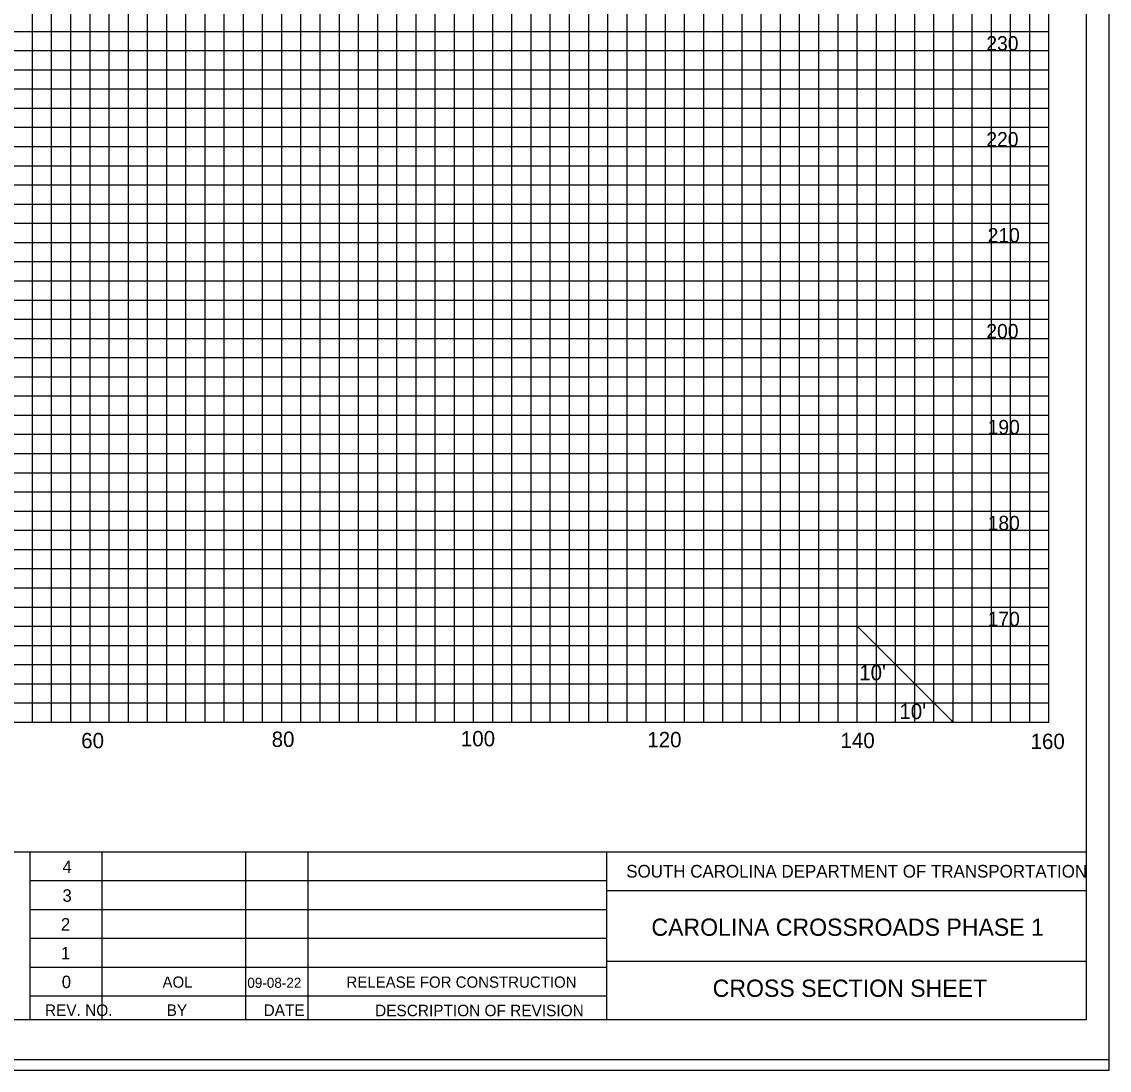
# Model space of a CAD drawing. Extents: x 967 to 1326, y 964 to 3144.
# Drawn here: x 1212.9 to 1326.3, y 963.7 to 1073 of the extents above; entities that cross this region are included whole.
import ezdxf

# ---------------------------------------------------------------- set-up
doc = ezdxf.new("R2010")
doc.units = 0
for name, color, linetype in [('Default', 7, 'Continuous'), ('RD_GPK_XS_Cell', 7, 'Continuous'), ('RD_XS_ExGround', 7, 'Continuous'), ('RD_XS_ExPaveRet', 7, 'Continuous'), ('RD_XS_Misc_Line', 7, 'Continuous'), ('RD_XS_TX_Elev_EX', 7, 'Continuous'), ('RD_XS_TX_Elev_PR', 7, 'Continuous'), ('RD_XS_TX_Station', 7, 'Continuous')]:
    doc.layers.add(name, color=color, linetype=linetype)

msp = doc.modelspace()

# ---------------------------------------------------------------- linework, layer by layer
at = {"layer": 'RD_GPK_XS_Cell'}
for p, q in [((1220, 1000), (1220, 1170)), ((1230, 1000), (1230, 1170)), ((1240, 1000), (1240, 1170)), ((1250, 1000), (1250, 1170)), ((1260, 1000), (1260, 1170)), ((1270, 1000), (1270, 1170)), ((1280, 1000), (1280, 1170)), ((1290, 1000), (1290, 1170)), ((1300, 1000), (1300, 1170)), ((1310, 1000), (1310, 1170)), ((1320, 1000), (1320, 1170)), ((1000, 1070), (1320, 1070)), ((1000, 1060), (1320, 1060)), ((1000, 1050), (1320, 1050)), ((1000, 1040), (1320, 1040)), ((1000, 1030), (1320, 1030)), ((1000, 1020), (1320, 1020)), ((1000, 1010), (1320, 1010)), ((1000, 1000), (1320, 1000))]:
    msp.add_line(p, q, dxfattribs=at)
at = {"layer": 'RD_XS_ExGround'}
for p, q in [((1214, 1000), (1214, 1170)), ((1216, 1000), (1216, 1170)), ((1218, 1000), (1218, 1170)), ((1222, 1000), (1222, 1170)), ((1224, 1000), (1224, 1170)), ((1226, 1000), (1226, 1170)), ((1228, 1000), (1228, 1170)), ((1232, 1000), (1232, 1170)), ((1234, 1000), (1234, 1170)), ((1236, 1000), (1236, 1170)), ((1238, 1000), (1238, 1170)), ((1242, 1000), (1242, 1170)), ((1244, 1000), (1244, 1170)), ((1246, 1000), (1246, 1170)), ((1248, 1000), (1248, 1170)), ((1252, 1000), (1252, 1170)), ((1254, 1000), (1254, 1170)), ((1256, 1000), (1256, 1170)), ((1258, 1000), (1258, 1170)), ((1262, 1000), (1262, 1170)), ((1264, 1000), (1264, 1170)), ((1266, 1000), (1266, 1170)), ((1268, 1000), (1268, 1170)), ((1272, 1000), (1272, 1170)), ((1274, 1000), (1274, 1170)), ((1276, 1000), (1276, 1170)), ((1278, 1000), (1278, 1170)), ((1282, 1000), (1282, 1170)), ((1284, 1000), (1284, 1170)), ((1286, 1000), (1286, 1170)), ((1288, 1000), (1288, 1170)), ((1292, 1000), (1292, 1170)), ((1294, 1000), (1294, 1170)), ((1296, 1000), (1296, 1170)), ((1298, 1000), (1298, 1170)), ((1302, 1000), (1302, 1170)), ((1304, 1000), (1304, 1170)), ((1306, 1000), (1306, 1170)), ((1308, 1000), (1308, 1170)), ((1312, 1000), (1312, 1170)), ((1314, 1000), (1314, 1170)), ((1316, 1000), (1316, 1170)), ((1318, 1000), (1318, 1170)), ((1000, 1072), (1320, 1072)), ((1000, 1068), (1320, 1068)), ((1000, 1066), (1320, 1066)), ((1000, 1064), (1320, 1064)), ((1000, 1062), (1320, 1062)), ((1000, 1058), (1320, 1058)), ((1000, 1056), (1320, 1056)), ((1000, 1054), (1320, 1054)), ((1000, 1052), (1320, 1052)), ((1000, 1048), (1320, 1048)), ((1000, 1046), (1320, 1046)), ((1000, 1044), (1320, 1044)), ((1000, 1042), (1320, 1042)), ((1000, 1038), (1320, 1038)), ((1000, 1036), (1320, 1036)), ((1000, 1034), (1320, 1034)), ((1000, 1032), (1320, 1032)), ((1000, 1028), (1320, 1028)), ((1000, 1026), (1320, 1026)), ((1000, 1024), (1320, 1024)), ((1000, 1022), (1320, 1022)), ((1000, 1018), (1320, 1018)), ((1000, 1016), (1320, 1016)), ((1000, 1014), (1320, 1014)), ((1000, 1012), (1320, 1012)), ((1000, 1008), (1320, 1008)), ((1000, 1006), (1320, 1006)), ((1000, 1004), (1320, 1004)), ((1000, 1002), (1320, 1002))]:
    msp.add_line(p, q, dxfattribs=at)
at = {"layer": 'RD_XS_ExPaveRet'}
for points in [[(967.41, 963.72), (1326.28, 963.72), (1326.28, 1183.72), (967.41, 1183.72)], [(988.52, 964.84), (1326.28, 964.84), (1326.28, 1182.6), (988.52, 1182.6)]]:
    msp.add_lwpolyline(points, close=True, dxfattribs=at)
at = {"layer": 'RD_XS_Misc_Line'}
msp.add_line((1300, 1010), (1310, 1000), dxfattribs=at)
at = {"layer": 'RD_XS_TX_Elev_EX'}
for p, q in [((1323.89, 1178.46), (1323.89, 968.98)), ((996.11, 986.49), (1323.89, 986.49)), ((1213.76, 968.94), (1213.76, 986.49)), ((1221.26, 968.95), (1221.26, 986.48)), ((1236.26, 968.95), (1236.26, 986.48)), ((1242.76, 968.95), (1242.76, 986.48)), ((1273.88, 968.98), (1273.88, 986.49)), ((1213.76, 983.48), (1273.88, 983.48)), ((1323.93, 982.43), (1273.88, 982.43)), ((1213.76, 980.48), (1273.88, 980.48)), ((1213.76, 977.48), (1273.88, 977.48)), ((1213.76, 974.48), (1273.88, 974.48)), ((1323.89, 975.04), (1273.88, 975.04)), ((1213.76, 971.48), (1273.88, 971.48)), ((1323.89, 968.98), (996.11, 968.98))]:
    msp.add_line(p, q, dxfattribs=at)
at = {"layer": 'RD_XS_TX_Station'}
msp.add_lwpolyline([(967.41, 963.72), (1326.28, 963.72), (1326.28, 1183.72), (967.41, 1183.72)], close=True, dxfattribs=at)

# ---------------------------------------------------------------- texts
at = {"layer": 'Default'}
for s, p in [('230', (1313.47, 1070)), ('220', (1313.47, 1060)), ('210', (1313.61, 1050)), ('200', (1313.47, 1040)), ('190', (1313.61, 1030)), ('180', (1313.61, 1020)), ('170', (1313.61, 1010))]:
    msp.add_text(s, height=1.5, dxfattribs=at).set_placement(p)
at = {"layer": 'RD_XS_Misc_Line'}
for s, height, p in [("10'", 1.6, (1300.21, 1004.36)), ("10'", 1.6, (1304.4, 1000.32)), ('100', 1.6, (1258.67, 997.48)), ('60', 1.6, (1219.08, 997.28)), ('80', 1.6, (1238.94, 997.42)), ('120', 1.6, (1278.11, 997.38)), ('140', 1.6, (1298.26, 997.29)), ('160', 1.6, (1318.08, 997.2)), ('4', 1.3, (1217.13, 984.28)), ('SOUTH CAROLINA DEPARTMENT OF TRANSPORTATION', 1.32, (1275.92, 983.8)), ('3', 1.3, (1217.13, 981.28)), ('2', 1.3, (1216.97, 978.28)), ('1', 1.3, (1216.97, 975.28)), ('0', 1.3, (1217.05, 972.28)), ('REV. NO.', 1.2, (1215.3, 969.38)), ('BY', 1.2, (1227.99, 969.38)), ('DATE', 1.2, (1238.1, 969.38)), ('DESCRIPTION OF REVISION', 1.2, (1249.73, 969.35))]:
    msp.add_text(s, height=height, dxfattribs=at).set_placement(p)
for s, p in [('CAROLINA CROSSROADS PHASE 1', (1278.54, 977.73)), ('CROSS SECTION SHEET', (1284.93, 971.37))]:
    msp.add_text(s, height=1.8, rotation=0, dxfattribs=at).set_placement(p)
at = {"layer": 'RD_XS_TX_Elev_PR'}
for s, height, p in [('AOL', 1.17, (1227.56, 972.32)), ('09-08-22', 1.053, (1236.4, 972.31)), ('RELEASE FOR CONSTRUCTION', 1.17, (1246.74, 972.32))]:
    msp.add_text(s, height=height, dxfattribs=at).set_placement(p)

doc.saveas('drawing.dxf')
